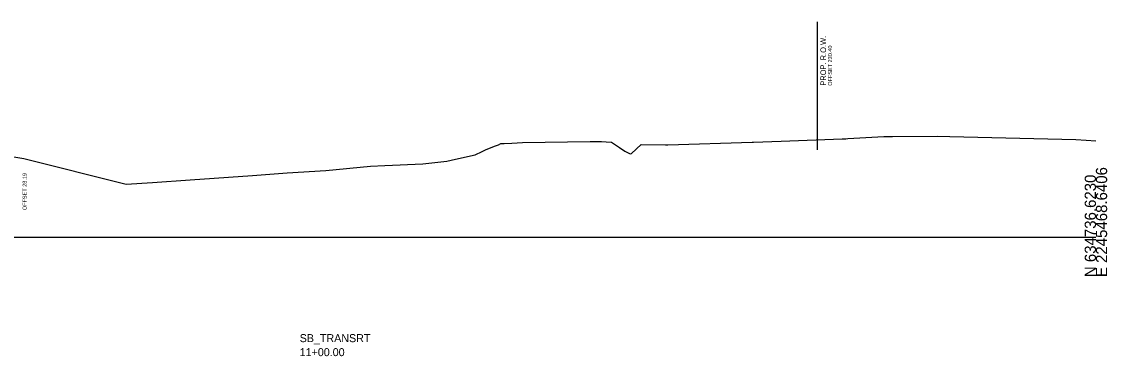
# Model space of a CAD drawing. Extents: x -26 to 669, y -22 to 6560.
# Drawn here: x 331.5 to 602.8, y 970.2 to 1053.8 of the extents above; entities that cross this region are included whole.
import ezdxf

# ---------------------------------------------------------------- set-up
doc = ezdxf.new("R2010")
doc.units = 0
for name, color, linetype in [('DESIGN - ROW - Right-of-Way and Easement Labels', 7, 'Continuous'), ('DESIGN - ROW - Right-of-Way Linework', 7, 'Continuous'), ('DESIGN - SHEET - Light Grid', 7, 'Continuous'), ('DESIGN - TYPICAL - Subgrade Tie Text', 7, 'Continuous'), ('DESIGN - TYPICAL - Warning Text', 7, 'Continuous'), ('SURVEY - GROUND - Top of Ground', 7, 'Continuous')]:
    doc.layers.add(name, color=color, linetype=linetype)

msp = doc.modelspace()

# ---------------------------------------------------------------- linework, layer by layer
at = {"layer": 'DESIGN - ROW - Right-of-Way Linework'}
msp.add_line((530.4, 1021.8), (530.4, 1053.8), dxfattribs=at)
at = {"layer": 'DESIGN - SHEET - Light Grid'}
msp.add_line((300, 1000), (600, 1000), dxfattribs=at)
at = {"layer": 'SURVEY - GROUND - Top of Ground'}
for p, q in [((323.36, 1021.04), (332.05, 1019.59)), ((332.05, 1019.59), (357.6, 1013.21))]:
    msp.add_line(p, q, dxfattribs=at)
msp.add_lwpolyline([(357.6, 1013.21), (364.18, 1013.61), (373.64, 1014.3), (389.23, 1015.38), (397.87, 1016.01), (407.57, 1016.65), (418.69, 1017.75), (422.26, 1017.9), (431.79, 1018.28), (437.8, 1018.96), (439.97, 1019.47), (444.84, 1020.56), (446.63, 1021.42), (447.46, 1021.76), (449.67, 1022.7), (450.67, 1023.05), (451.24, 1023.37), (452.07, 1023.41), (453.98, 1023.49), (456.7, 1023.59), (473.59, 1023.9), (476.42, 1023.88), (477.6, 1023.81), (478.96, 1023.75), (480.92, 1022.39), (482.25, 1021.47), (483.57, 1020.79), (483.97, 1020.84), (486.31, 1023.14), (492.39, 1023.01), (492.97, 1023.01), (514.08, 1023.68), (514.43, 1023.69), (521.3, 1023.95), (536.55, 1024.54), (537.46, 1024.57), (537.99, 1024.6), (547.02, 1025.15), (549.15, 1025.11), (560.51, 1025.21), (563.52, 1025.14), (595.01, 1024.36), (597.55, 1024.17), (600, 1024.02)], dxfattribs=at)

# ---------------------------------------------------------------- texts
at = {"layer": 'DESIGN - ROW - Right-of-Way and Easement Labels'}
for s, height, p in [('PROP. R.O.W.', 1.4, (532.55, 1037.8)), ('OFFSET 230.40', 1, (534.05, 1037.8))]:
    msp.add_text(s, height=height, rotation=90, dxfattribs=at).set_placement(p)
at = {"layer": 'DESIGN - SHEET - Light Grid'}
for s, p in [('N 634736.6230', (600, 990)), ('E 2245468.6406', (602.8, 990))]:
    msp.add_text(s, height=2.8, rotation=90, dxfattribs=at).set_placement(p)
at = {"layer": 'DESIGN - TYPICAL - Subgrade Tie Text'}
msp.add_text('OFFSET 28.19', height=1, rotation=90, dxfattribs=at).set_placement((332.76, 1006.73))
at = {"layer": 'DESIGN - TYPICAL - Warning Text'}
for s, p in [('SB_TRANSRT', (401, 973.75)), ('11+00.00', (401, 970.25))]:
    msp.add_text(s, height=2, dxfattribs=at).set_placement(p)

doc.saveas('drawing.dxf')
